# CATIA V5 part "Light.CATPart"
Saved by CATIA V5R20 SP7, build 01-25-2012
Part number: Light
Bounding box of the stored display mesh (mm): x -250 to 0, y -90.636 to 90.636, z -90.65 to 90.65
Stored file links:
  E:\#03 University\#02 영남 이공대\#01 2021\#02 여름 방학\#01 Documents\K-Move Page02 ASD01\Light.CATPart

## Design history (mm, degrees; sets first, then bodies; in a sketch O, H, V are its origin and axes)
Set1 "Reference Data"
  Point1 "Center Point": (0, 0, 0)
Body1 (main body)
  Body2 "Light Main Body"
    Sketch1 on zx-plane, origin (0, 0, 0), H (-1, 0, 0), V (0, 0, 1)
      line L1 (0, 0) -> (0, 90)
      point P1 (0, 90)
      arc A1 centre (24.2953, -359.3437) radius 450 from (0, 90) to (221.9631, 44.918) cw
      arc A2 centre (200, 0) radius 50 from (221.9631, 44.918) to (250, 0) cw
      point P4 (200, 0)
      point P5 (250, 0)
      axis line L2 (0, 0) -> (250, 0)
      radius A2 = 50
      radius A1 = 450
      distance P1 H = 90
      distance V P5 = 250
      vertical: L1 V
      coincidence: P5 H, P4 H
      tangency: A2 A1
      horizontal: L2 H
    Shaft1: profile Sketch1, axis Sketch1.L2, angle 360
    Fillet1: radius 10, on edge [face of Shaft1 from Sketch1.L1 | face of Shaft1 from Sketch1.A1]
  Assemble1: tool Body2
  Body3 "Hole Boss"
    Sketch2 on xy-plane, origin (0, 0, 0), H (0, 1, 0), V (-1, 0, 0)
      circle A1 centre (0, 150) radius 7.5
      point P1 (0, 150)
      circle A2 centre (0, 150) radius 12.5
      radius A2 = 12.5
      radius A1 = 7.5
      distance P1 H = 150
      coincidence: P1 V
    Pad1: profile Sketch2, direction (0, 0, -1), length 80
  Assemble2: tool Body3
